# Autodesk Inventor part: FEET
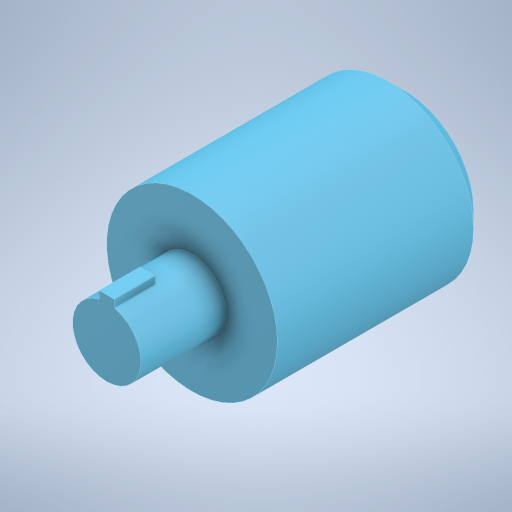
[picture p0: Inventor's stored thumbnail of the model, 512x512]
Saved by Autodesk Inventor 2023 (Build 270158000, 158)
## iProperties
Created: 2025-07
Part Number: FEET
Material: Generic
Document SubType Name: Modeling
Designer: erjon
Density: 1 g/cm^3
Appearance: Default
Author: erjon
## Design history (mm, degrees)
feature "Base1"
body "Solid1"
